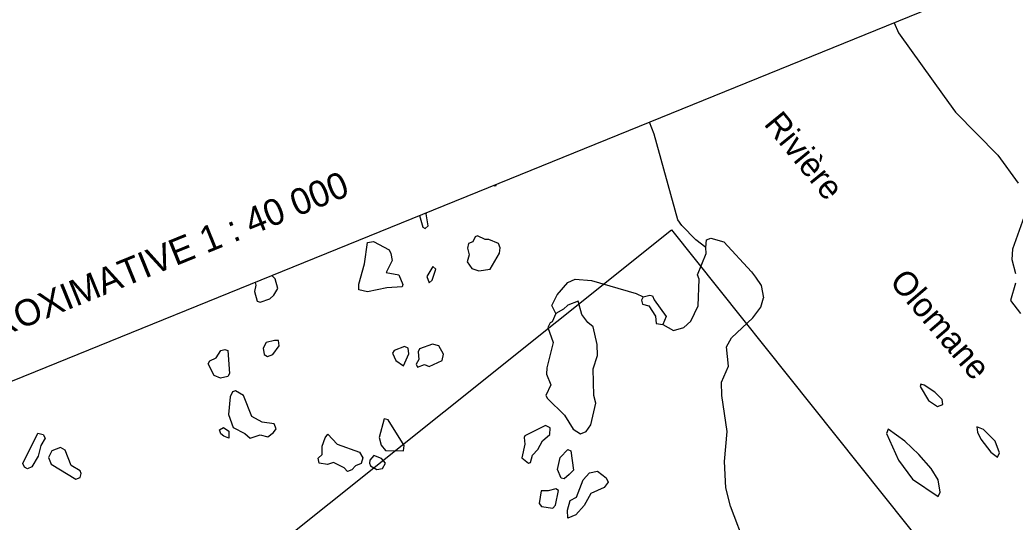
# Model space of a CAD drawing. Extents: x 362852 to 366875, y 5563573 to 5566479.
# Drawn here: x 366131.8 to 366283.3, y 5565952.7 to 5566029.1 of the extents above; entities that cross this region are included whole.
import ezdxf

# ---------------------------------------------------------------- set-up
doc = ezdxf.new("R2010")
doc.units = 0
doc.layers.add('Niveau 63', color=7, linetype='Continuous')

msp = doc.modelspace()

# ---------------------------------------------------------------- linework, layer by layer
at = {"layer": 'Niveau 63'}
msp.add_lwpolyline([(366082.77, 5565630.49), (366453.96, 5565781.16), (366340.96, 5566059.55), (365969.77, 5565908.88)], close=True, dxfattribs=at)
for points in [[(366264.86, 5566028.66), (366265.53, 5566027.13), (366272.49, 5566017.47)], [(366272.49, 5566017.47), (366274.22, 5566015.07), (366280.64, 5566008.52), (366283.77, 5566004.25)], [(366236.21, 5565994.47), (366234.68, 5565995.65), (366232.56, 5565997.84), (366231.96, 5565998.69), (366228.36, 5566011.73), (366227.67, 5566013.56)], [(366204.33, 5566004.09), (366204.16, 5566003.81), (366203.94, 5566003.93)], [(366192.67, 5565999.36), (366193.15, 5565997.56), (366193.53, 5565997.39), (366193.98, 5565997.77), (366193.65, 5565999.63), (366193.7, 5565999.78)], [(366284.9, 5565999.91), (366282.88, 5565994.26), (366282.79, 5565992.67), (366283.34, 5565990.52)], [(366109.31, 5565900.03), (366231, 5565997.2), (366281.03, 5565934.55)], [(366203.18, 5565995.72), (366202.64, 5565995.73), (366201.48, 5565996.24), (366201.1, 5565996.1), (366200.76, 5565995.33), (366200.1, 5565995.08), (366199.94, 5565994.37), (366200.21, 5565993.4), (366199.92, 5565992.32), (366200.59, 5565991.29), (366201.68, 5565990.96), (366203.41, 5565991.2), (366204.84, 5565993.62), (366204.95, 5565994.46), (366204.65, 5565995.1), (366203.18, 5565995.72)], [(366187.67, 5565988.34), (366184.73, 5565987.74), (366183.44, 5565988.05), (366183.43, 5565988.91), (366184.28, 5565992.02), (366184.75, 5565995.26), (366185.67, 5565995.39), (366188.02, 5565994.15), (366188.3, 5565993.56), (366188.49, 5565992.51), (366187.57, 5565990.71), (366189.49, 5565990.32), (366190.09, 5565988.88), (366190.01, 5565988.53), (366187.67, 5565988.34)], [(366236.21, 5565994.47), (366236.34, 5565995.65), (366237, 5565995.9), (366238.97, 5565995.37), (366243.18, 5565990.81), (366243.77, 5565989.96)], [(366229.68, 5565982.8), (366231.32, 5565981.87), (366232.85, 5565982.35), (366233.94, 5565983.3), (366235.04, 5565985.6), (366235.19, 5565989.68), (366234.95, 5565990.34), (366236.28, 5565993.58), (366236.21, 5565994.47)], [(366193.76, 5565990.07), (366194.12, 5565989.14), (366194.56, 5565989.53), (366195.15, 5565991.2), (366194.68, 5565991.6), (366193.76, 5565990.07)], [(366167.62, 5565989.19), (366167.73, 5565988.75), (366167.55, 5565987.82), (366167.96, 5565986.31), (366168.4, 5565986.16), (366169.86, 5565986.67), (366170.5, 5565987.23), (366171.08, 5565988.26), (366170.68, 5565989.72), (366170.2, 5565990.24)], [(366213.39, 5565984.45), (366212.81, 5565985.68), (366213.58, 5565987.31), (366215.23, 5565989.17), (366216.33, 5565989.65), (366218.82, 5565989.48), (366225.64, 5565987.48), (366226.69, 5565986.97)], [(366243.77, 5565989.96), (366244.64, 5565988.69), (366245.02, 5565986.85)], [(366283.36, 5565989.08), (366282.6, 5565986.43), (366284.12, 5565984.44)], [(366226.69, 5565986.97), (366227.71, 5565987.25), (366228.12, 5565987.14), (366228.36, 5565986.53), (366230.18, 5565984.01), (366229.68, 5565982.8)], [(366213.39, 5565984.45), (366212.86, 5565983.17), (366212.53, 5565983.05), (366212.17, 5565982.32), (366212.98, 5565980.06), (366212.04, 5565976.21), (366211.99, 5565975.23), (366212.61, 5565973.59), (366211.85, 5565971.96), (366212.12, 5565971.53), (366214.7, 5565968.98), (366216.05, 5565966.86), (366217.17, 5565966.17), (366218.01, 5565966.49), (366218.7, 5565967.5), (366219.47, 5565970.8), (366219.18, 5565971.98), (366219.07, 5565976.06), (366219.74, 5565978.09), (366219.7, 5565979.74), (366219.09, 5565982.45), (366218.25, 5565983.09), (366217.36, 5565984.31), (366216.8, 5565986.35), (366215.2, 5565985.73), (366214.54, 5565985.1), (366213.39, 5565984.45)], [(366226.69, 5565986.97), (366226.44, 5565986.5), (366226.58, 5565985.85), (366227.53, 5565985.62), (366228.56, 5565984.04), (366228.66, 5565982.95), (366229.68, 5565982.8)], [(366262.38, 5565939.66), (366263.86, 5565936.21), (366263.69, 5565935.23), (366263.05, 5565934.4), (366260.34, 5565933.36), (366256.39, 5565933.72), (366253.41, 5565934.78), (366248.34, 5565938.36), (366246.32, 5565940.86), (366242.34, 5565948.88), (366239.99, 5565955.16), (366239.29, 5565957.96), (366239.05, 5565961.94), (366239.46, 5565966.49), (366238.65, 5565971.97), (366238.62, 5565974), (366239.67, 5565976.44), (366239.35, 5565979.37), (366240.12, 5565980.74), (366243.39, 5565983.81), (366244.6, 5565985.4), (366245.02, 5565986.85)], [(366170.57, 5565980.34), (366169.3, 5565980.02), (366168.88, 5565979.16), (366169.01, 5565978.24), (366169.52, 5565977.9), (366170.31, 5565978.21), (366171.3, 5565979.55), (366171.2, 5565980.37), (366170.57, 5565980.34)], [(366192.15, 5565976.75), (366192.33, 5565976.29), (366193.41, 5565976.7), (366194.12, 5565976.38), (366196.08, 5565977.29), (366196.29, 5565978.28), (366195.6, 5565979.52), (366194.64, 5565979.79), (366192.66, 5565979.09), (366192.45, 5565978.64), (366192.54, 5565977.44), (366192.15, 5565976.75)], [(366163.49, 5565978.81), (366163.75, 5565975.32), (366163.5, 5565974.85), (366162.35, 5565974.63), (366161.4, 5565975.01), (366160.5, 5565976.81), (366160.75, 5565977.28), (366161.71, 5565977.7), (366162.41, 5565978.83), (366163.05, 5565978.97), (366163.49, 5565978.81)], [(366188.78, 5565978.84), (366188.52, 5565978.42), (366189.04, 5565977.33), (366190.22, 5565976.5), (366191.03, 5565978.3), (366190.91, 5565979.17), (366190.37, 5565979.45), (366188.78, 5565978.84)], [(366268.92, 5565973.69), (366268.85, 5565973.34), (366270.08, 5565971.24), (366271.45, 5565970.32), (366272.29, 5565970.64), (366272.16, 5565971.39), (366271.06, 5565972.47), (366269.45, 5565973.57), (366268.92, 5565973.69)], [(366165.88, 5565972.01), (366164.64, 5565972.71), (366164.17, 5565972.53), (366163.83, 5565971.76), (366163.57, 5565969.08), (366164.31, 5565967.12), (366166.05, 5565966.23), (366166.86, 5565965.52), (366168.39, 5565966), (366169.58, 5565965.7), (366170.45, 5565966.36), (366170.82, 5565966.93), (366170.54, 5565967.68), (366168.72, 5565967.95), (366167.16, 5565968.8), (366165.88, 5565972.01)], [(366187.29, 5565968.46), (366186.51, 5565965.59), (366186.8, 5565964.41), (366187.48, 5565963.6), (366190.23, 5565963.58), (366190.3, 5565964.36), (366187.88, 5565968.31), (366187.29, 5565968.46)], [(366212.53, 5565967.08), (366211.81, 5565967.44), (366208.7, 5565965.87), (366208.59, 5565965.62), (366208.67, 5565964.57), (366208.22, 5565962.52), (366209.24, 5565961.68), (366209.56, 5565961.81), (366209.83, 5565962.93), (366210.64, 5565963.77), (366211.37, 5565965.07), (366212.5, 5565966.04), (366212.53, 5565967.08)], [(366135.02, 5565964.38), (366134.61, 5565962.78), (366133.64, 5565961.12), (366133, 5565960.82), (366132.53, 5565961.07), (366132.31, 5565961.63), (366134.57, 5565966.25), (366135.4, 5565966.03), (366135.67, 5565965.49), (366135.02, 5565964.38)], [(366162.88, 5565965.82), (366162.42, 5565966.18), (366162.21, 5565966.74), (366162.81, 5565967.13), (366163.63, 5565966.54), (366163.66, 5565965.48), (366162.88, 5565965.82)], [(366182.89, 5565961.31), (366182.33, 5565960.66), (366181.68, 5565960.41), (366181.19, 5565960.98), (366179.54, 5565961.79), (366178.63, 5565961.5), (366177.37, 5565961.72), (366177.25, 5565962.47), (366177.84, 5565963.02), (366177.85, 5565964.26), (366178.27, 5565965.54), (366178.69, 5565966.13), (366180.14, 5565964.6), (366183.5, 5565963.36), (366184.05, 5565962.5), (366183.78, 5565961.65), (366182.89, 5565961.31)], [(366263.98, 5565966.87), (366263.69, 5565966.22), (366265.52, 5565962.15), (366267.68, 5565959.28), (366271.59, 5565956.65), (366271.88, 5565957.29), (366271.59, 5565959.16), (366270.5, 5565960.89), (366268.62, 5565963.01), (366266.5, 5565965.04), (366263.98, 5565966.87)], [(366277.47, 5565967.2), (366277.55, 5565966.43), (366278.07, 5565965.34), (366279.59, 5565963.35), (366280.62, 5565962.62), (366280.9, 5565963.27), (366280.23, 5565965.04), (366278.49, 5565966.79), (366277.47, 5565967.2)], [(366138.03, 5565964.09), (366136.71, 5565963.58), (366136.19, 5565962.58), (366136.58, 5565961.55), (366140.36, 5565959.24), (366141, 5565959.54), (366141.15, 5565960.13), (366140.99, 5565960.55), (366139.62, 5565961.32), (366138.73, 5565963.65), (366138.03, 5565964.09)], [(366185.68, 5565962.86), (366185.09, 5565962.15), (366185.05, 5565961.7), (366185.21, 5565961.28), (366186.17, 5565960.74), (366187.03, 5565960.86), (366187.46, 5565961.72), (366186.87, 5565962.4), (366185.68, 5565962.86)], [(366215.41, 5565959.97), (366214.65, 5565959.3), (366214.19, 5565959.4), (366213.67, 5565960.75), (366214.05, 5565962.56), (366215.2, 5565963.75), (366215.7, 5565963.57), (366216.07, 5565960.65), (366215.41, 5565959.97)], [(366216.43, 5565953.82), (366215.23, 5565953.31), (366215.17, 5565954.57), (366215.59, 5565956.02), (366216.56, 5565956.55), (366217.54, 5565959.18), (366218.52, 5565960.25), (366219.72, 5565960.49), (366221.03, 5565959.44), (366221.37, 5565958.82), (366220.73, 5565957.99), (366218.73, 5565957.06), (366217.69, 5565955.27), (366216.43, 5565953.82)], [(366212.24, 5565957.47), (366211.16, 5565957.49), (366210.84, 5565955.54), (366211.22, 5565955.1), (366212.93, 5565954.84), (366213.34, 5565955.32), (366213.78, 5565957.52), (366213.4, 5565957.81), (366212.24, 5565957.47)]]:
    msp.add_lwpolyline(points, dxfattribs=at)

# ---------------------------------------------------------------- texts
for s, height, rotation, p in [('Rivière', 3.68, 309.208, (366244.93, 5566013.24)), ('ÉCHELLE APPROXIMATIVE 1 : 40 000', 4, 22.1263, (366094.4, 5565966.79)), ('Olomane', 3.68, 310.5167, (366264.04, 5565989.23))]:
    msp.add_text(s, height=height, rotation=rotation, dxfattribs=at).set_placement(p)

doc.saveas('drawing.dxf')
